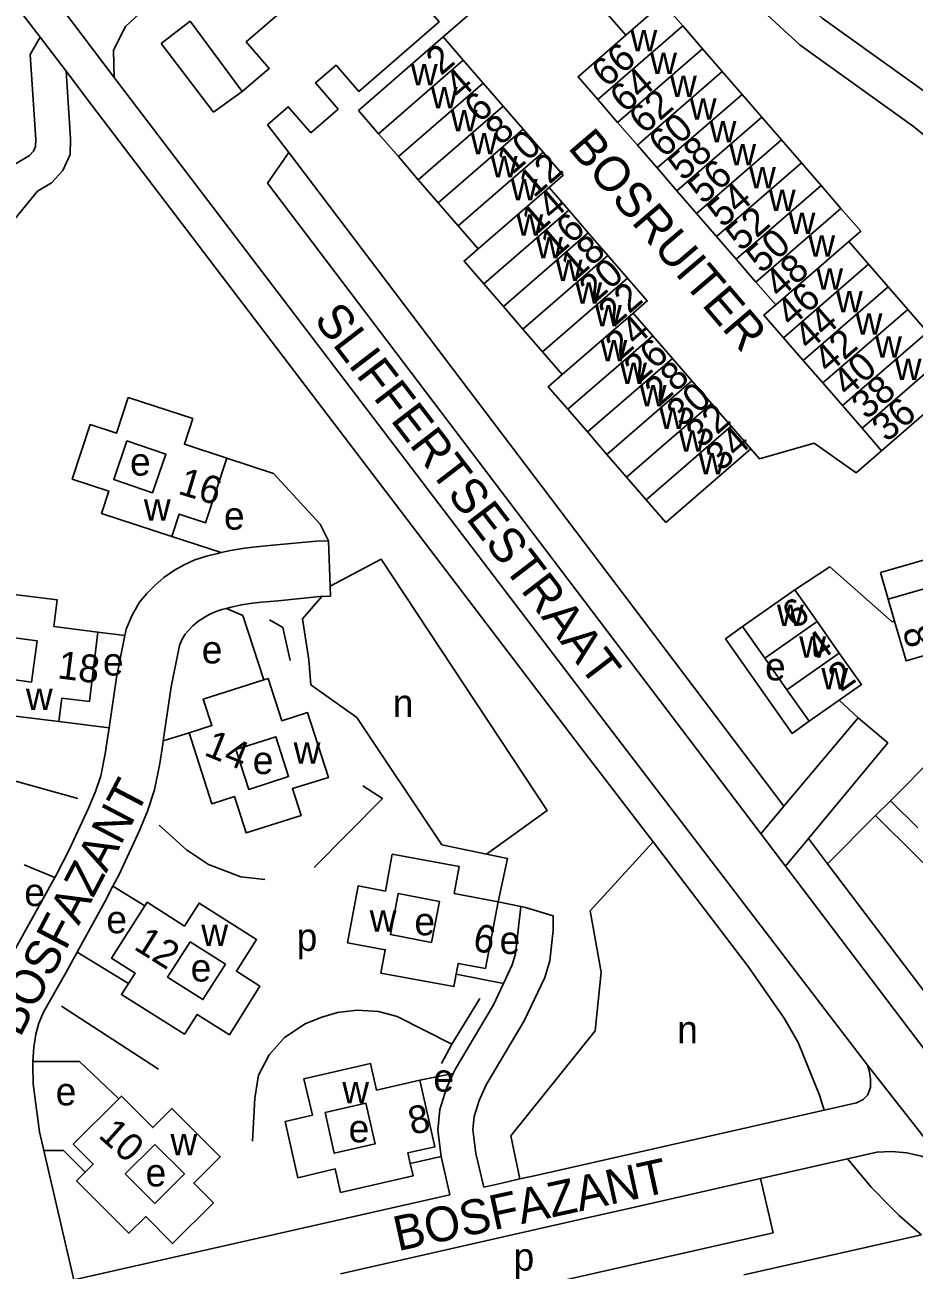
# Model space of a CAD drawing. Extents: x 155854 to 157362, y 383621 to 384685.
# Drawn here: x 156844.9 to 156972.9, y 384097.6 to 384276.9 of the extents above; entities that cross this region are included whole.
import ezdxf

# ---------------------------------------------------------------- set-up
doc = ezdxf.new("R2010")
doc.units = 0
for name, color, linetype in [('BLT_Basislijn', 7, 'Continuous'), ('BLT_Bebouwing', 7, 'Continuous'), ('BLT_Centroide', 7, 'Continuous'), ('BLT_Huisnummer', 7, 'Continuous'), ('BLT_Huisnummer_ tussenligend', 7, 'Continuous'), ('BLT_Onderverdeling_panden', 7, 'Continuous'), ('BLT_Straatnaam', 7, 'Continuous'), ('BLT_Vlakafsluiter', 7, 'Continuous')]:
    doc.layers.add(name, color=color, linetype=linetype)

msp = doc.modelspace()

# ---------------------------------------------------------------- linework, layer by layer
at = {"layer": 'BLT_Basislijn'}
for p, q in [((156832.88, 384293.85), (156847.1, 384275.16)), ((156850.18, 384279.37), (156857.78, 384269.37)), ((156864.54, 384274.25), (156868.69, 384277.45)), ((156876.19, 384267.35), (156868.69, 384277.45)), ((156847.1, 384275.16), (156850.83, 384270.25)), ((156872.04, 384264.36), (156864.54, 384274.25)), ((156850.83, 384270.25), (156854.52, 384265.41)), ((156876.19, 384267.35), (156872.04, 384264.36)), ((156890.02, 384264.81), (156886.07, 384261.38)), ((156882.9, 384258.56), (156879.81, 384262.53)), ((156882.9, 384258.56), (156879.81, 384254.13)), ((156882.9, 384258.56), (156931.2, 384194.76)), ((156879.81, 384254.13), (156976.52, 384126.62)), ((156873.96, 384214.56), (156880.69, 384212.36)), ((156866.07, 384203.27), (156873.16, 384200.95)), ((156888.83, 384196.1), (156888.63, 384202.66)), ((156969.2, 384194.23), (156968.06, 384198.08)), ((156888.88, 384194.67), (156888.83, 384196.1)), ((156887.66, 384194.64), (156888.88, 384194.67)), ((156931.2, 384194.76), (156954.16, 384164.43)), ((156855.43, 384189.49), (156859.31, 384189.02)), ((156948.23, 384190.29), (156945.76, 384188.55)), ((156849.81, 384176.63), (156857.03, 384175.74)), ((156868.57, 384175.01), (156864.83, 384173.85)), ((156967.37, 384163.08), (156969.51, 384165.2)), ((156957.69, 384159.77), (156960.45, 384156.12)), ((156844.78, 384156.01), (156849.22, 384154.18)), ((156960.45, 384156.12), (156993.84, 384112.01)), ((156857.58, 384152.91), (156862.17, 384150.09)), ((156916.31, 384149.98), (156913.04, 384150.68)), ((156859.8, 384138.9), (156852.42, 384143.42)), ((156907, 384140.24), (156913.79, 384138.9)), ((156906.35, 384130.19), (156910.42, 384136.76)), ((156864.16, 384126.58), (156850.2, 384135.63)), ((156904.89, 384127.41), (156906.35, 384130.19)), ((156901.77, 384124.99), (156906.58, 384125.96)), ((156918.44, 384111.28), (156959.98, 384120.69)), ((156851.95, 384096.23), (156847.64, 384114.86)), ((156900.37, 384113.01), (156904.85, 384114.02)), ((156950.8, 384110.82), (156963.31, 384113.65)), ((156963.31, 384113.65), (156967.57, 384114.62)), ((156910.96, 384109.59), (156913.56, 384110.18)), ((156913.56, 384110.18), (156916.15, 384110.77)), ((156916.15, 384110.77), (156918.44, 384111.28)), ((156932.88, 384106.76), (156950.8, 384110.82)), ((156950.8, 384110.82), (156952.6, 384103.03)), ((156851.95, 384096.23), (156906.09, 384108.49)), ((156924.98, 384104.97), (156932.88, 384106.76)), ((156924.98, 384104.97), (156890.35, 384097.12)), ((156892.05, 384089.31), (156952.6, 384103.03)), ((156966.33, 384101.01), (156973.99, 384102.74)), ((156948.38, 384096.94), (156966.33, 384101.01))]:
    msp.add_line(p, q, dxfattribs=at)
for points in [[(156916.14, 384308.64), (156908.63, 384302.07), (156911.91, 384298.31), (156909.23, 384295.99), (156905.94, 384299.74), (156894.67, 384289.96), (156897.9, 384286.17), (156893.32, 384282.2), (156890.06, 384285.96), (156876.77, 384274.47), (156880.08, 384270.65), (156876.19, 384267.35)], [(156931.15, 384308.44), (156935.05, 384303.64), (156938.05, 384298.8), (156945.7, 384290.76), (156959.68, 384277.91), (156975.88, 384266.29), (156983.29, 384260.25), (156990.7, 384253.38), (157026.7, 384213.15), (157030.78, 384209.21), (157035.83, 384205.87), (157040, 384202.49), (157044.37, 384197.32), (157047.31, 384191.85), (157049.01, 384186.14), (157050.93, 384173.32)], [(156923.6, 384300.59), (156928.11, 384304.25), (156930.97, 384300.74), (156934.08, 384295.73), (156942.19, 384287.2), (156956.52, 384274.02), (156972.84, 384262.32), (156980.01, 384256.47), (156987.13, 384249.87), (157023.1, 384209.68), (157027.64, 384205.29), (157032.87, 384201.84), (157036.48, 384198.91), (157040.21, 384194.49), (157042.67, 384189.93), (157044.12, 384185.05), (157046.03, 384172.27)], [(156913.34, 384284.97), (156914.55, 384283.58), (156920.23, 384288.33), (156931.42, 384275.43)], [(156908.38, 384280.63), (156906.32, 384282.97), (156905.73, 384283.41), (156904.99, 384283.61), (156904.26, 384283.53), (156903.58, 384283.18), (156901.28, 384281.16), (156904.55, 384277.39), (156892.98, 384267.36), (156889.71, 384271.13), (156886.76, 384268.57), (156890.02, 384264.81)], [(156905.14, 384275.19), (156909.66, 384279.17), (156908.38, 384280.63)], [(156861.32, 384278.5), (156859.38, 384276.7), (156857.64, 384273.27), (156857.78, 384269.37)], [(156847.1, 384275.16), (156845.66, 384272.65), (156846.48, 384260.45), (156846.45, 384259.43), (156846.14, 384258.75), (156845.55, 384258.11), (156843.4, 384256.83), (156841.7, 384254.73)], [(156850.83, 384270.25), (156851.48, 384260.55), (156851.42, 384258.29), (156850.37, 384255.97), (156848.75, 384254.19), (156846.72, 384252.99), (156842.66, 384247.98), (156841.01, 384244.43)], [(156857.78, 384269.37), (156929.01, 384175.79), (156966.22, 384127.15)], [(156854.52, 384265.41), (156925.03, 384172.75), (156935.33, 384159.29)], [(156886.07, 384261.38), (156882.81, 384265.14), (156879.81, 384262.53)], [(156968.24, 384215.6), (156964.59, 384212.44), (156958.53, 384216.69), (156950.67, 384214.43), (156949.4, 384215.89)], [(156880.69, 384212.36), (156887.4, 384205.04), (156888.63, 384202.66)], [(156873.16, 384200.95), (156874.51, 384201.26), (156876.54, 384201.61), (156878.19, 384201.78), (156880.62, 384202), (156886.87, 384202.62), (156888.63, 384202.66)], [(156968.06, 384198.08), (156984.09, 384202.69)], [(156859.31, 384189.02), (156859.5, 384189.93), (156860.34, 384191.95), (156861.42, 384193.8), (156862.44, 384195.04), (156863.64, 384196.27), (156864.93, 384197.36), (156866.45, 384198.42), (156867.84, 384199.2), (156869.38, 384199.89), (156871.04, 384200.46), (156872.62, 384200.83), (156873.16, 384200.95)], [(156888.83, 384196.1), (156896.18, 384200.01), (156920.07, 384163.8), (156911.35, 384157.54)], [(156955.76, 384195.58), (156960.77, 384198.91), (156969.73, 384190.99), (156970.1, 384191.1)], [(156873.93, 384192.92), (156874.41, 384193.04), (156876.08, 384193.41), (156877.65, 384193.68), (156878.96, 384193.82), (156881.37, 384194.03), (156887.37, 384194.63), (156887.66, 384194.64)], [(156911.35, 384157.54), (156904.93, 384158.88), (156892.71, 384177.19), (156886.08, 384181.93), (156885.77, 384185.51), (156884.85, 384191.41), (156887.66, 384194.64)], [(156864.83, 384173.85), (156865.97, 384181.61), (156867.18, 384187.58), (156867.52, 384188.38), (156868, 384189.21), (156868.41, 384189.7), (156869.1, 384190.41), (156869.81, 384191.01), (156870.7, 384191.63), (156871.45, 384192.05), (156872.32, 384192.44), (156873.26, 384192.76), (156873.93, 384192.92)], [(156879.3, 384182.63), (156876.27, 384191.89), (156873.93, 384192.92)], [(156883.09, 384185.43), (156882.02, 384190.17), (156880.1, 384191.25)], [(156857.03, 384175.74), (156858.09, 384182.99), (156859.31, 384189.02)], [(156957.79, 384176.66), (156955.34, 384174.92), (156945.76, 384188.55)], [(156962.14, 384179.69), (156964.84, 384177.16)], [(156964.84, 384177.16), (156954.16, 384164.43)], [(156964.84, 384177.16), (156969.11, 384173.54), (156957.69, 384159.77)], [(156849.22, 384154.18), (156849.36, 384154.43), (156851.29, 384158.15), (156854.08, 384164.17), (156855.07, 384166.53), (156855.84, 384168.83), (156856.46, 384171.97), (156856.85, 384174.54), (156857.03, 384175.74)], [(156857.58, 384152.91), (156858.47, 384154.62), (156861.4, 384160.94), (156862.56, 384163.71), (156863.58, 384166.77), (156864.35, 384170.59), (156864.76, 384173.36), (156864.83, 384173.85)], [(156836.96, 384171.49), (156842.02, 384168.49), (156852.52, 384165.56)], [(156886.54, 384155.6), (156896.38, 384165.55), (156893.54, 384167.37)], [(156954.16, 384164.43), (156950.84, 384160.47)], [(156879.47, 384153.86), (156875.98, 384154.25), (156871.36, 384156.06), (156868.17, 384158.16), (156864.26, 384161.72)], [(156960.45, 384156.12), (156967.37, 384163.08)], [(156979.21, 384151.32), (156967.37, 384163.08)], [(156935.33, 384159.29), (156926.3, 384149.36), (156927.88, 384140.56), (156927.02, 384132.1), (156914.87, 384116.99), (156916.15, 384110.77)], [(156935.33, 384159.29), (156949.04, 384141.37), (156954.19, 384133.9), (156956.21, 384130.43), (156959.31, 384122.82), (156959.98, 384120.69)], [(156957.69, 384159.77), (156954.39, 384155.79)], [(156913.04, 384150.68), (156914.37, 384156.91), (156911.35, 384157.54)], [(156842.78, 384142.55), (156843.82, 384144.37), (156849.22, 384154.18)], [(156852.42, 384143.42), (156856.41, 384150.66), (156857.58, 384152.91)], [(156910.96, 384109.59), (156909.84, 384114.45), (156909.38, 384117.88), (156909.56, 384119.75), (156910.29, 384122.04), (156911.32, 384124.31), (156916.77, 384133.52), (156919.74, 384139.79), (156920.47, 384142.16), (156920.95, 384146.52), (156920.93, 384148.66), (156916.96, 384149.84), (156916.31, 384149.98)], [(156916.31, 384149.98), (156915.55, 384143.18), (156915.06, 384141.6), (156913.79, 384138.9)], [(156846.07, 384127.69), (156846.18, 384129.75), (156846.46, 384131.62), (156846.91, 384133.2), (156847.57, 384134.79), (156848.59, 384136.58), (156850.8, 384140.46), (156852.42, 384143.42)], [(156913.79, 384138.9), (156912.35, 384135.86), (156906.88, 384126.62), (156906.58, 384125.96)], [(156906.35, 384130.19), (156898.5, 384134.18), (156895.82, 384134.89), (156892.73, 384135.06), (156889.91, 384134.73), (156887.53, 384134.02), (156885.24, 384133.08), (156882.26, 384131.14), (156880.05, 384128.66), (156878.55, 384125.7), (156878.03, 384122.41), (156877.67, 384116.19)], [(156847.64, 384114.86), (156847.02, 384117.53), (156846.22, 384123.37), (156846.11, 384124.44), (156846.04, 384127.12), (156846.07, 384127.69)], [(156846.07, 384127.69), (156852.75, 384127.69), (156858.42, 384122.31)], [(156906.58, 384125.96), (156905.62, 384123.84), (156904.63, 384120.76), (156904.35, 384117.78), (156904.85, 384114.02)], [(156959.98, 384120.69), (156964.6, 384121.72), (156965.57, 384122.19), (156966.23, 384122.89), (156966.64, 384123.97), (156966.64, 384125.19), (156966.48, 384126.2), (156966.22, 384127.15)], [(156853.59, 384111.74), (156850.48, 384114.88), (156847.64, 384114.86)], [(156904.85, 384114.02), (156904.91, 384113.55), (156906.09, 384108.49)], [(156963.31, 384113.65), (156966.79, 384109.52), (156969.42, 384106.83)], [(156967.57, 384114.62), (156969.7, 384114.71), (156971.85, 384114.52), (156973.96, 384114.04), (156975.98, 384113.29), (156977.86, 384112.29)], [(156969.42, 384106.83), (156970.74, 384105.49), (156972.71, 384103.76), (156973.99, 384102.74)]]:
    msp.add_lwpolyline(points, dxfattribs=at)
at = {"layer": 'BLT_Bebouwing'}
for p, q in [((156931.42, 384275.43), (156936.76, 384280.06)), ((156939.61, 384276.78), (156942.46, 384273.49)), ((156892.92, 384264.59), (156905.14, 384275.19)), ((156905.14, 384275.19), (156908.02, 384271.87)), ((156942.46, 384273.49), (156945.3, 384270.21)), ((156908.02, 384271.87), (156910.89, 384268.55)), ((156945.3, 384270.21), (156948.15, 384266.92)), ((156910.89, 384268.55), (156913.77, 384265.23)), ((156927.38, 384266.18), (156930.23, 384262.9)), ((156948.15, 384266.92), (156950.99, 384263.64)), ((156913.77, 384265.23), (156916.64, 384261.92)), ((156930.23, 384262.9), (156933.07, 384259.61)), ((156950.99, 384263.64), (156953.84, 384260.36)), ((156895.79, 384261.27), (156898.67, 384257.96)), ((156916.64, 384261.92), (156919.52, 384258.6)), ((156953.84, 384260.36), (156956.69, 384257.07)), ((156933.07, 384259.61), (156935.92, 384256.33)), ((156898.67, 384257.96), (156901.54, 384254.64)), ((156956.69, 384257.07), (156959.53, 384253.79)), ((156935.92, 384256.33), (156938.76, 384253.04)), ((156901.54, 384254.64), (156904.41, 384251.32)), ((156959.53, 384253.79), (156962.38, 384250.5)), ((156938.76, 384253.04), (156941.61, 384249.76)), ((156904.41, 384251.32), (156907.29, 384248)), ((156923.19, 384250.26), (156926.01, 384246.99)), ((156941.61, 384249.76), (156944.46, 384246.48)), ((156926.01, 384246.99), (156928.84, 384243.73)), ((156944.46, 384246.48), (156947.3, 384243.19)), ((156963.53, 384245.75), (156966.36, 384242.49)), ((156928.84, 384243.73), (156931.67, 384240.46)), ((156947.3, 384243.19), (156950.15, 384239.91)), ((156966.36, 384242.49), (156969.18, 384239.23)), ((156910.96, 384239.66), (156913.79, 384236.4)), ((156950.15, 384239.91), (156952.99, 384236.62)), ((156969.18, 384239.23), (156972, 384235.97)), ((156913.79, 384236.4), (156916.61, 384233.13)), ((156972, 384235.97), (156974.83, 384232.71)), ((156916.61, 384233.13), (156919.44, 384229.87)), ((156935.29, 384232.18), (156938.11, 384228.92)), ((156954.13, 384231.89), (156956.95, 384228.63)), ((156938.11, 384228.92), (156940.93, 384225.67)), ((156956.95, 384228.63), (156959.77, 384225.38)), ((156940.93, 384225.67), (156943.75, 384222.41)), ((156959.77, 384225.38), (156962.6, 384222.12)), ((156923.06, 384221.59), (156925.88, 384218.33)), ((156943.75, 384222.41), (156946.58, 384219.15)), ((156962.6, 384222.12), (156965.42, 384218.86)), ((156925.88, 384218.33), (156928.7, 384215.07)), ((156928.7, 384215.07), (156931.52, 384211.82)), ((156931.52, 384211.82), (156934.35, 384208.56)), ((156948.23, 384190.29), (156955.76, 384195.58)), ((156955.76, 384195.58), (156958.95, 384191.03)), ((156970.1, 384191.1), (156969.2, 384194.23)), ((156911.23, 384141.07), (156913.04, 384150.68))]:
    msp.add_line(p, q, dxfattribs=at)
for points in [[(156936.76, 384280.06), (156939.61, 384276.78)], [(156927.38, 384266.18), (156924.54, 384269.47), (156931.42, 384275.43)], [(156895.79, 384261.27), (156892.92, 384264.59)], [(156919.52, 384258.6), (156922.39, 384255.28), (156920.36, 384253.52)], [(156920.36, 384253.52), (156923.19, 384250.26)], [(156962.38, 384250.5), (156965.22, 384247.22), (156963.53, 384245.75)], [(156910.16, 384244.68), (156907.29, 384248)], [(156910.96, 384239.66), (156908.13, 384242.92), (156910.16, 384244.68)], [(156931.67, 384240.46), (156934.5, 384237.2), (156932.46, 384235.44)], [(156932.46, 384235.44), (156935.29, 384232.18)], [(156954.13, 384231.89), (156951.3, 384235.15), (156952.99, 384236.62)], [(156922.27, 384226.61), (156919.44, 384229.87)], [(156923.06, 384221.59), (156920.24, 384224.84), (156922.27, 384226.61)], [(156980.47, 384226.2), (156968.24, 384215.6)], [(156873.96, 384214.56), (156867.88, 384216.55), (156869.08, 384220.24), (156859.79, 384223.28), (156858.11, 384218.13), (156854.3, 384219.38), (156851.73, 384211.53), (156856.97, 384209.82), (156855.92, 384206.59), (156866.07, 384203.27)], [(156946.58, 384219.15), (156949.4, 384215.89)], [(156968.24, 384215.6), (156965.42, 384218.86)], [(156949.4, 384215.89), (156937.18, 384205.29)], [(156866.07, 384203.27), (156867.13, 384206.49), (156870.92, 384205.26), (156873.96, 384214.56)], [(156937.18, 384205.29), (156934.35, 384208.56)], [(156855.43, 384189.49), (156849.08, 384190.29), (156849.56, 384194.15), (156839.85, 384195.36), (156839.15, 384189.73), (156835.17, 384190.21), (156834.17, 384181.97), (156839.62, 384181.31), (156839.2, 384177.94), (156849.81, 384176.63)], [(156969.2, 384194.23), (156974.52, 384195.76)], [(156958.95, 384191.03), (156962.14, 384186.49)], [(156977.07, 384186.9), (156971.75, 384185.37), (156970.1, 384191.1)], [(156849.81, 384176.63), (156850.23, 384180.01), (156854.19, 384179.51), (156855.43, 384189.49)], [(156951.42, 384185.74), (156948.23, 384190.29)], [(156954.61, 384181.2), (156951.42, 384185.74)], [(156962.14, 384186.49), (156965.34, 384181.94), (156962.14, 384179.69)], [(156868.57, 384175.01), (156871.83, 384164.8), (156875.08, 384165.84), (156876.75, 384160.6), (156884.67, 384163.1), (156883.42, 384166.99), (156888.6, 384168.55), (156885.61, 384177.92), (156881.9, 384176.74), (156879.94, 384182.83), (156879.3, 384182.63)], [(156879.3, 384182.63), (156870.58, 384179.84), (156871.83, 384176.04), (156868.57, 384175.01)], [(156957.79, 384176.66), (156954.61, 384181.2)], [(156962.14, 384179.69), (156957.79, 384176.66)], [(156969.51, 384165.2), (156976.01, 384171.74), (156979.93, 384167.85)], [(156973.43, 384161.31), (156969.51, 384165.2)], [(156913.04, 384150.68), (156906.71, 384151.88), (156907.43, 384155.74), (156897.8, 384157.53), (156896.8, 384152.21), (156892.87, 384152.96), (156891.35, 384144.75), (156896.78, 384143.77), (156896.15, 384140.41), (156906.67, 384138.46), (156907, 384140.24)], [(156859.8, 384138.9), (156860.77, 384140.41), (156857.39, 384142.55), (156862.17, 384150.09)], [(156862.17, 384150.09), (156862.49, 384150.6), (156867.87, 384147.18), (156869.99, 384150.48), (156878.25, 384145.22), (156875.35, 384140.67), (156878.73, 384138.52), (156874.34, 384131.53), (156869.69, 384134.45), (156867.88, 384131.59), (156858.8, 384137.32), (156859.8, 384138.9)], [(156907, 384140.24), (156907.29, 384141.8), (156911.23, 384141.07)], [(156901.77, 384124.99), (156895.53, 384123.56), (156894.67, 384127.38), (156885.08, 384125.2), (156886.3, 384119.93), (156882.38, 384119.04), (156884.22, 384110.93), (156889.59, 384112.2), (156890.36, 384108.83), (156900.79, 384111.21), (156900.37, 384113.01)], [(156900.37, 384113.01), (156900.03, 384114.51), (156903.93, 384115.39), (156901.77, 384124.99)], [(156858.42, 384122.31), (156851.88, 384115.76), (156854.76, 384112.91), (156853.59, 384111.74)], [(156853.59, 384111.74), (156852.34, 384110.49), (156859.89, 384102.94), (156862.3, 384105.34), (156866.18, 384101.45), (156872.04, 384107.33), (156869.21, 384110.16), (156873.02, 384113.97), (156866.08, 384120.92), (156863.32, 384118.16), (156858.8, 384122.69), (156858.42, 384122.31)]]:
    msp.add_lwpolyline(points, dxfattribs=at)
for points in [[(156859.6, 384217.06), (156865.2, 384215.14), (156863.29, 384209.57), (156857.69, 384211.49)], [(156840.82, 384189.03), (156846.66, 384188.23), (156845.85, 384182.3), (156840.02, 384183.1)], [(156881.02, 384174.43), (156881.02, 384174.43), (156875.29, 384172.58), (156877.14, 384166.85), (156882.87, 384168.7)], [(156898.65, 384151.86), (156897.53, 384145.95), (156903.44, 384144.83), (156904.57, 384150.73)], [(156868.69, 384144.91), (156865.46, 384139.83), (156870.54, 384136.6), (156873.77, 384141.68)], [(156888.12, 384120.34), (156889.45, 384114.47), (156895.32, 384115.8), (156893.99, 384121.67)], [(156863.61, 384115.74), (156859.36, 384111.49), (156863.62, 384107.23), (156867.87, 384111.49)]]:
    msp.add_lwpolyline(points, close=True, dxfattribs=at)
at = {"layer": 'BLT_Onderverdeling_panden'}
for p, q in [((156927.38, 384266.18), (156939.61, 384276.78)), ((156930.23, 384262.9), (156942.46, 384273.49)), ((156895.79, 384261.27), (156908.02, 384271.87)), ((156933.07, 384259.61), (156945.3, 384270.21)), ((156898.67, 384257.96), (156910.89, 384268.55)), ((156935.92, 384256.33), (156948.15, 384266.92)), ((156901.54, 384254.64), (156913.77, 384265.23)), ((156938.76, 384253.04), (156950.99, 384263.64)), ((156904.41, 384251.32), (156916.64, 384261.92)), ((156941.61, 384249.76), (156953.84, 384260.36)), ((156907.29, 384248), (156919.52, 384258.6)), ((156944.46, 384246.48), (156956.69, 384257.07)), ((156920.36, 384253.52), (156910.16, 384244.68)), ((156947.3, 384243.19), (156959.53, 384253.79)), ((156923.19, 384250.26), (156910.96, 384239.66)), ((156950.15, 384239.91), (156962.38, 384250.5)), ((156926.01, 384246.99), (156913.79, 384236.4)), ((156952.99, 384236.62), (156963.53, 384245.75)), ((156928.84, 384243.73), (156916.61, 384233.13)), ((156954.13, 384231.89), (156966.36, 384242.49)), ((156931.67, 384240.46), (156919.44, 384229.87)), ((156956.95, 384228.63), (156969.18, 384239.23)), ((156922.27, 384226.61), (156932.46, 384235.44)), ((156959.77, 384225.38), (156972, 384235.97)), ((156923.06, 384221.59), (156935.29, 384232.18)), ((156962.6, 384222.12), (156974.83, 384232.71)), ((156925.88, 384218.33), (156938.11, 384228.92)), ((156965.42, 384218.86), (156977.65, 384229.46)), ((156928.7, 384215.07), (156940.93, 384225.67)), ((156931.52, 384211.82), (156943.75, 384222.41)), ((156934.35, 384208.56), (156946.58, 384219.15)), ((156951.42, 384185.74), (156958.95, 384191.03)), ((156954.61, 384181.2), (156962.14, 384186.49))]:
    msp.add_line(p, q, dxfattribs=at)
at = {"layer": 'BLT_Vlakafsluiter'}
msp.add_lwpolyline([(156966.22, 384127.15), (156977.86, 384112.29)], dxfattribs=at)

# ---------------------------------------------------------------- texts
at = {"layer": 'BLT_Centroide'}
for s, p in [('w', (156932.07, 384273.12)), ('w', (156934.91, 384269.84)), ('w', (156900.46, 384268.22)), ('w', (156937.77, 384266.56)), ('w', (156903.34, 384264.91)), ('w', (156940.61, 384263.28)), ('w', (156906.21, 384261.59)), ('w', (156943.46, 384260)), ('w', (156909.09, 384258.28)), ('w', (156946.3, 384256.69)), ('w', (156911.96, 384254.97)), ('w', (156949.15, 384253.41)), ('w', (156914.84, 384251.66)), ('w', (156951.99, 384250.12)), ('w', (156915.66, 384246.59)), ('w', (156954.84, 384246.84)), ('w', (156918.48, 384243.31)), ('w', (156957.68, 384243.56)), ('w', (156921.31, 384240.06)), ('w', (156958.83, 384238.81)), ('w', (156924.14, 384236.81)), ('w', (156961.66, 384235.56)), ('w', (156926.97, 384233.53)), ('w', (156964.48, 384232.31)), ('w', (156967.3, 384229.03)), ('w', (156927.76, 384228.5)), ('w', (156930.59, 384225.25)), ('w', (156970.12, 384225.78)), ('w', (156933.41, 384222)), ('w', (156936.23, 384218.75)), ('w', (156939.05, 384215.47)), ('e', (156860.04, 384212.04)), ('w', (156941.88, 384212.22)), ('w', (156862.03, 384205.57)), ('e', (156873.56, 384204.26)), ('w', (156953.17, 384190.38)), ('w', (156956.37, 384185.81)), ('e', (156870.37, 384184.99)), ('e', (156856.14, 384183.25)), ('e', (156951.45, 384182.55)), ('w', (156959.55, 384181.28)), ('w', (156845.05, 384178.31)), ('n', (156897.86, 384177.26)), ('w', (156883.59, 384170.56)), ('e', (156877.71, 384169.06)), ('e', (156844.82, 384150.06)), ('e', (156856.63, 384146.14)), ('w', (156894.54, 384146.38)), ('w', (156870.3, 384144.31)), ('e', (156900.98, 384145.85)), ('p', (156884.03, 384143.6)), ('e', (156913.24, 384143.15)), ('e', (156868.77, 384139.19)), ('n', (156938.81, 384130.27)), ('e', (156903.71, 384123.32)), ('e', (156849.34, 384121.36)), ('w', (156890.59, 384121.67)), ('e', (156891.51, 384116.04)), ('w', (156865.86, 384114.19)), ('e', (156862.28, 384109.69)), ('p', (156915.25, 384097.57))]:
    msp.add_text(s, height=4, dxfattribs=at).set_placement(p)
at = {"layer": 'BLT_Huisnummer'}
for s, rotation, p in [('2', 40.9063, (156904.82, 384269.54)), ('66', 40.9063, (156928.65, 384267.78)), ('6', 40.9063, (156910.35, 384262.69)), ('60', 40.9063, (156936.89, 384257.66)), ('10', 40.9063, (156915.01, 384255.24)), ('56', 40.9063, (156942.52, 384250.97)), ('14', 40.9063, (156918.59, 384246.68)), ('52', 40.9063, (156947.97, 384244.2)), ('18', 40.9063, (156924.23, 384240.15)), ('48', 40.9063, (156953.56, 384237.41)), ('22', 40.9063, (156929.63, 384233.29)), ('44', 40.9063, (156957.76, 384229.92)), ('26', 40.9063, (156933.32, 384225.25)), ('40', 40.9063, (156963.33, 384223.25)), ('30', 40.9063, (156939.48, 384218.89)), ('36', 40.9063, (156969, 384216.72)), ('34', 40.9063, (156945.08, 384212.52)), ('16', 343.3002, (156866.79, 384209.45)), ('6', 35.0996, (156955.75, 384189.8)), ('8', 286.0309, (156971.2, 384189.83)), ('18', 352.5002, (156849.48, 384182.88)), ('2', 35.0996, (156962.37, 384180.8)), ('14', 338.0002, (156870.54, 384171.84)), ('6', 348.0002, (156909.22, 384143.72)), ('12', 328.0002, (156860.42, 384143.94)), ('8', 13.0002, (156900.61, 384117.09)), ('10', 318.0002, (156855.33, 384116.88))]:
    msp.add_text(s, height=4, rotation=rotation, dxfattribs=at).set_placement(p)
at = {"layer": 'BLT_Huisnummer_ tussenligend'}
for s, rotation, p in [('4', 40.9063, (156907.52, 384266)), ('64', 40.9063, (156931.31, 384264.12)), ('62', 40.9063, (156934.04, 384261.07)), ('8', 40.9063, (156913.38, 384259.45)), ('58', 40.9063, (156939.63, 384254.33)), ('12', 40.9063, (156918.17, 384251.94)), ('54', 40.9063, (156945.34, 384247.61)), ('16', 40.9063, (156921.31, 384243.31)), ('50', 40.9063, (156950.92, 384241.02)), ('20', 40.9063, (156926.87, 384236.75)), ('46', 40.9063, (156955.21, 384233.3)), ('24', 40.9063, (156930.62, 384228.59)), ('42', 40.9063, (156960.59, 384226.6)), ('28', 40.9063, (156936.3, 384221.99)), ('38', 40.9063, (156966.07, 384219.97)), ('32', 40.9063, (156942.27, 384215.87)), ('4', 35.0996, (156959.1, 384185.08))]:
    msp.add_text(s, height=4, rotation=rotation, dxfattribs=at).set_placement(p)
at = {"layer": 'BLT_Straatnaam'}
for s, height, rotation, p in [('BOSRUITER', 5, 310.4543, (156922.94, 384259.23)), ('SLIFFERTSESTRAAT', 4.9999, 307.4543, (156886.37, 384234.47)), ('BOSFAZANT', 5, 62.3513, (156844.21, 384131.03)), ('BOSFAZANT', 5, 12.3513, (156898.59, 384100.35))]:
    msp.add_text(s, height=height, rotation=rotation, dxfattribs=at).set_placement(p)

doc.saveas('drawing.dxf')
